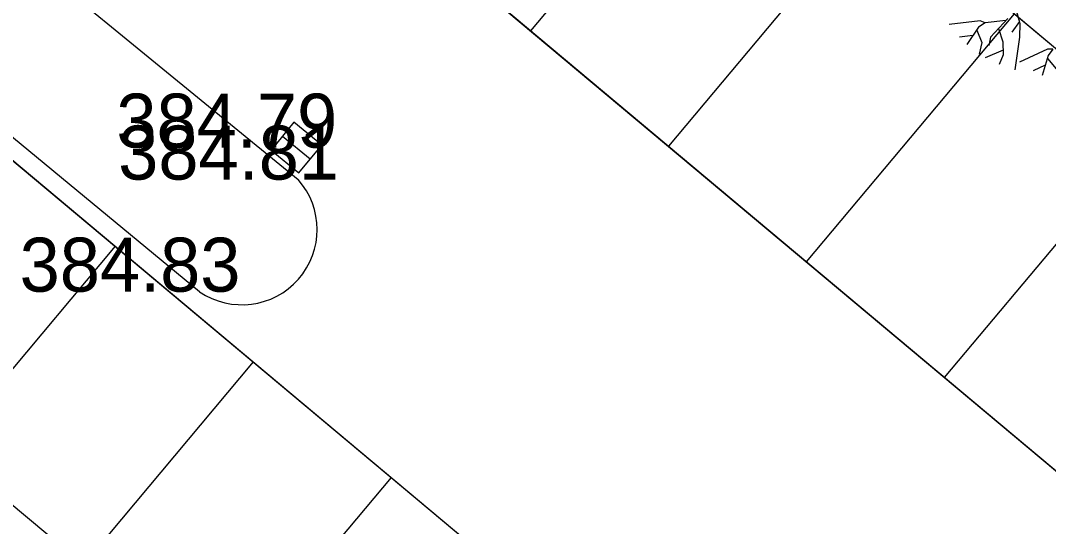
# Model space of a CAD drawing. Extents: x -438233 to -437334, y -1133133 to -1132623.
# Drawn here: x -438087.94 to -438073.66, y -1132995.04 to -1132988.01 of the extents above; entities that cross this region are included whole.
import ezdxf

# ---------------------------------------------------------------- set-up
doc = ezdxf.new("R2010")
doc.units = 0
for name, color, linetype in [('Vrstva 1', 7, 'Continuous'), ('Vrstva 10', 7, 'Continuous'), ('Vrstva 27', 7, 'Continuous'), ('Vrstva 3', 7, 'Continuous'), ('Vrstva 50', 7, 'Continuous'), ('Vrstva 55', 7, 'Continuous')]:
    doc.layers.add(name, color=color, linetype=linetype)

msp = doc.modelspace()

# ---------------------------------------------------------------- linework, layer by layer
at = {"layer": 'Vrstva 1'}
for p, q in [((-438091.577, -1132973.302), (-438066.281, -1132994.494)), ((-438094.467, -1132976.751), (-438069.171, -1132997.943)), ((-438098.32, -1132981.35), (-438073.024, -1133002.543)), ((-438077.971, -1132984.701), (-438080.86, -1132988.15)), ((-438076.054, -1132986.306), (-438078.944, -1132989.755)), ((-438074.144, -1132987.747), (-438074.06, -1132988.05)), ((-438074.138, -1132987.912), (-438077.028, -1132991.361)), ((-438074.257, -1132988.008), (-438074.545, -1132988.039)), ((-438074.228, -1132987.977), (-438074.467, -1132988.24)), ((-438074.614, -1132988.013), (-438075.041, -1132988.064)), ((-438074.637, -1132988.101), (-438074.8, -1132988.338)), ((-438074.661, -1132988.14), (-438074.59, -1132988.313)), ((-438074.545, -1132988.039), (-438074.637, -1132988.101)), ((-438074.545, -1132988.039), (-438074.614, -1132988.013)), ((-438074.356, -1132988.117), (-438074.296, -1132988.305)), ((-438074.068, -1132988.02), (-438074.174, -1132988.168)), ((-438074.06, -1132988.05), (-438074.066, -1132988.237)), ((-438074.716, -1132988.216), (-438074.9, -1132988.238)), ((-438074.467, -1132988.24), (-438074.492, -1132988.354)), ((-438074.066, -1132988.237), (-438074.131, -1132988.691)), ((-438074.59, -1132988.313), (-438074.625, -1132988.473)), ((-438074.295, -1132988.421), (-438074.541, -1132988.526)), ((-438074.296, -1132988.305), (-438074.295, -1132988.482)), ((-438073.675, -1132988.403), (-438074.066, -1132988.587)), ((-438073.602, -1132988.406), (-438073.675, -1132988.403)), ((-438073.602, -1132988.406), (-438073.669, -1132988.494)), ((-438074.295, -1132988.482), (-438074.35, -1132988.619)), ((-438073.669, -1132988.494), (-438073.75, -1132988.769)), ((-438073.679, -1132988.537), (-438073.558, -1132988.68)), ((-438073.708, -1132988.628), (-438073.876, -1132988.708)), ((-438072.221, -1132989.517), (-438075.111, -1132992.966)), ((-438084.112, -1132989.773), (-438084.112, -1132989.773)), ((-438084.087, -1132990.217), (-438084.087, -1132990.217)), ((-438086.63, -1132991.144), (-438089.52, -1132994.593)), ((-438085.456, -1132991.774), (-438085.456, -1132991.774)), ((-438084.714, -1132992.749), (-438087.603, -1132996.199)), ((-438082.797, -1132994.355), (-438085.687, -1132997.804))]:
    msp.add_line(p, q, dxfattribs=at)
at = {"layer": 'Vrstva 10'}
for points in [[(-438100.332, -1132976.931), (-438084.087, -1132990.217)], [(-438101.653, -1132978.388), (-438085.456, -1132991.774)]]:
    msp.add_lwpolyline(points, dxfattribs=at)
msp.add_arc((-438084.868, -1132990.911), 1.045, 235.7438, 41.6088, dxfattribs=at)
at = {"layer": 'Vrstva 27'}
msp.add_line((-438084.306, -1132989.615), (-438083.918, -1132989.931), dxfattribs=at)
msp.add_lwpolyline([(-438084.464, -1132989.808), (-438084.077, -1132990.125), (-438083.76, -1132989.738), (-438084.147, -1132989.421)], close=True, dxfattribs=at)
at = {"layer": 'Vrstva 50'}
for points in [[(-438091.577, -1132973.302), (-438066.273, -1132994.5), (-438069.163, -1132997.95), (-438094.467, -1132976.751)], [(-438098.32, -1132981.35), (-438073.025, -1133002.541), (-438075.915, -1133005.991), (-438101.21, -1132984.8)]]:
    msp.add_lwpolyline(points, close=True, dxfattribs=at)
at = {"layer": 'Vrstva 55'}
msp.add_lwpolyline([(-438074.959, -1133013.61), (-438076.856, -1133009.846), (-438083.298, -1132998.719), (-438115.192, -1132972.054), (-438146.469, -1132953.711), (-438176.9, -1132931.48)], dxfattribs=at)

# ---------------------------------------------------------------- texts
at = {"layer": 'Vrstva 3'}
for s, p in [('384.79 ', (-438086.612, -1132989.773)), ('384.81 ', (-438086.587, -1132990.217)), ('384.83 ', (-438087.956, -1132991.774))]:
    msp.add_text(s, height=0.75, dxfattribs=at).set_placement(p)

doc.saveas('drawing.dxf')
